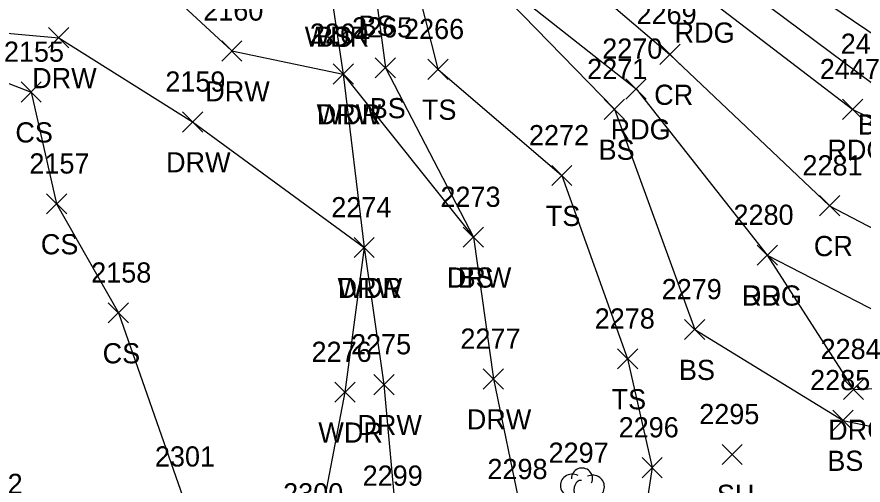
# Model space of a CAD drawing. Extents: x 1512665 to 1513714, y 110636 to 112816.
# Drawn here: x 1512914.5 to 1512998.3, y 110740.2 to 110786.6 of the extents above; entities that cross this region are included whole.
import ezdxf

# ---------------------------------------------------------------- set-up
doc = ezdxf.new("R2010")
doc.units = 0
for name, color, linetype in [('L_A', 7, 'Continuous'), ('L_I', 7, 'Continuous'), ('L_TIC', 7, 'Continuous'), ('LAWA', 7, 'Continuous'), ('LELB', 7, 'Continuous'), ('LTD', 7, 'Continuous'), ('P_A', 7, 'Continuous'), ('P_I', 7, 'Continuous'), ('P_TIC', 7, 'Continuous'), ('PEU', 7, 'Continuous'), ('PRC', 7, 'Continuous'), ('R_A', 7, 'Continuous'), ('R_I', 7, 'Continuous'), ('R_TIC', 7, 'Continuous'), ('RDG', 7, 'Continuous'), ('RDW', 7, 'Continuous')]:
    doc.layers.add(name, color=color, linetype=linetype)

msp = doc.modelspace()

# ---------------------------------------------------------------- linework, layer by layer
at = {"layer": 'L_TIC'}
for points in [[(1512949.992, 110780.568), (1512951.992, 110782.568)], [(1512951.992, 110780.568), (1512949.992, 110782.568)], [(1512949.992, 110780.568), (1512951.992, 110782.568)], [(1512951.992, 110780.568), (1512949.992, 110782.568)], [(1512955.195, 110780.418), (1512957.195, 110782.418)], [(1512957.195, 110780.418), (1512955.195, 110782.418)], [(1512945.819, 110779.951), (1512947.819, 110781.951)], [(1512947.819, 110779.951), (1512945.819, 110781.951)], [(1512914.917, 110778.166), (1512916.917, 110780.166)], [(1512916.917, 110778.166), (1512914.917, 110780.166)], [(1512972.652, 110776.453), (1512974.652, 110778.453)], [(1512974.652, 110776.453), (1512972.652, 110778.453)], [(1512967.46, 110769.893), (1512969.46, 110771.893)], [(1512969.46, 110769.893), (1512967.46, 110771.893)], [(1512917.439, 110767.088), (1512919.439, 110769.088)], [(1512919.439, 110767.088), (1512917.439, 110769.088)], [(1512958.698, 110763.789), (1512960.698, 110765.789)], [(1512960.698, 110763.789), (1512958.698, 110765.789)], [(1512947.89, 110762.758), (1512949.89, 110764.758)], [(1512949.89, 110762.758), (1512947.89, 110764.758)], [(1512923.557, 110756.288), (1512925.557, 110758.288)], [(1512925.557, 110756.288), (1512923.557, 110758.288)], [(1512980.607, 110754.641), (1512982.607, 110756.641)], [(1512982.607, 110754.641), (1512980.607, 110756.641)], [(1512973.971, 110751.732), (1512975.971, 110753.732)], [(1512975.971, 110751.732), (1512973.971, 110753.732)], [(1512945.989, 110748.434), (1512947.989, 110750.434)], [(1512947.989, 110748.434), (1512945.989, 110750.434)], [(1512995.294, 110745.637), (1512997.294, 110747.637)], [(1512997.294, 110745.637), (1512995.294, 110747.637)], [(1512984.316, 110742.266), (1512986.316, 110744.266)], [(1512986.316, 110742.266), (1512984.316, 110744.266)], [(1512976.394, 110740.958), (1512978.394, 110742.958)], [(1512978.394, 110740.958), (1512976.394, 110742.958)]]:
    msp.add_lwpolyline(points, dxfattribs=at)
at = {"layer": 'LAWA'}
msp.add_lwpolyline([(1512904.855, 110814.165), (1512921.132, 110807.474), (1512930.627, 110802.326), (1512939.473, 110793.102), (1512945.641, 110788.646), (1512946.819, 110780.951), (1512948.89, 110763.758), (1512946.989, 110749.434), (1512944.293, 110735.419), (1512940.962, 110714.938), (1512937.713, 110700.214), (1512950.792, 110688.786), (1512957.118, 110668.558), (1512971.82, 110659.404), (1512987.484, 110651.003), (1512993.751, 110649.548)], dxfattribs=at)
at = {"layer": 'LELB'}
for points in [[(1512700.679, 110948.394), (1512702.883, 110937.76), (1512707.699, 110928.255), (1512715.725, 110919.825), (1512729.364, 110912.396), (1512733.114, 110910.816), (1512749.564, 110901.484), (1512765.39, 110894.395), (1512774.129, 110890.874), (1512779.73, 110888.581), (1512784.329, 110885.95), (1512807.054, 110874.728), (1512832.029, 110862.151), (1512849.873, 110852.9), (1512877.541, 110837.789), (1512892.067, 110830.383), (1512907.918, 110822.224), (1512921.56, 110815.361), (1512936.611, 110807.627), (1512945.797, 110795.178), (1512949.896, 110789.739), (1512950.992, 110781.568)], [(1512965.768, 110809.049), (1512985.021, 110794.556), (1513002.316, 110782.838), (1513012.084, 110779.37), (1513025.948, 110772.452), (1513031.778, 110776.166)], [(1512936.611, 110807.627), (1512953.599, 110791.643), (1512956.195, 110781.418), (1512968.46, 110770.893), (1512974.971, 110752.732), (1512977.394, 110741.958), (1512974.26, 110721.428)], [(1512964.105, 110806.986), (1512983.29, 110791.889), (1512999.323, 110779.951), (1513012.212, 110774.48), (1513024.663, 110768.294), (1513032.242, 110771.906), (1513035.849, 110774.486)], [(1512958.132, 110793.433), (1512973.652, 110777.453), (1512981.607, 110755.641), (1512996.294, 110746.637), (1513006.992, 110744.376), (1513016.029, 110743.308), (1513026.953, 110745.673), (1513036.177, 110748.289)], [(1512902.912, 110747.196), (1512898.685, 110764.287), (1512894.988, 110776.221), (1512897.015, 110786.49), (1512915.917, 110779.166), (1512918.439, 110768.088), (1512924.557, 110757.288), (1512930.943, 110739.067), (1512912.467, 110736.35), (1512889.78, 110732.876)], [(1512950.992, 110781.568), (1512959.698, 110764.789)]]:
    msp.add_lwpolyline(points, dxfattribs=at)
at = {"layer": 'LTD'}
msp.add_arc((1512970.447, 110740.874), 1.047, 335.52715, 180.95627, dxfattribs=at)
for centre, major_axis, ratio, start_param, end_param in [((1512969.608, 110740.106), (1.21, -0.512), 0.895232, 1.570796, 4.712389), ((1512971.441, 110740.023), (-1.141, -0.483), 0.949671, 1.570796, 4.712389), ((1512970.191, 110739.898), (-0.208, -0.792), 0.645439, 3.141593, 6.283185)]:
    msp.add_ellipse(centre, major_axis=major_axis, ratio=ratio, start_param=start_param, end_param=end_param, dxfattribs=at)
at = {"layer": 'P_TIC'}
for points in [[(1512978.162, 110781.894), (1512980.162, 110783.894)], [(1512980.162, 110781.894), (1512978.162, 110783.894)], [(1512974.798, 110778.469), (1512976.798, 110780.469)], [(1512976.798, 110778.469), (1512974.798, 110780.469)], [(1512996.253, 110776.445), (1512998.253, 110778.445)], [(1512998.253, 110776.445), (1512996.253, 110778.445)], [(1512993.968, 110766.907), (1512995.968, 110768.907)], [(1512995.968, 110766.907), (1512993.968, 110768.907)], [(1512987.794, 110762.009), (1512989.794, 110764.009)], [(1512989.794, 110762.009), (1512987.794, 110764.009)]]:
    msp.add_lwpolyline(points, dxfattribs=at)
at = {"layer": 'PEU'}
for points in [[(1512701.918, 111049.687), (1512700.272, 111027.695), (1512701.575, 110993.777), (1512707.634, 110973.739), (1512708.973, 110956.468), (1512713.567, 110946.899), (1512719.219, 110936.541), (1512726.895, 110929.376), (1512741.614, 110919.596), (1512758.159, 110912.379), (1512787.354, 110896.005), (1512813.053, 110887.984), (1512838.367, 110874.777), (1512855.917, 110864.835), (1512882.817, 110848.349), (1512898.24, 110841.366), (1512913.486, 110833.402), (1512927.92, 110827.382), (1512944.462, 110817.212), (1512962.879, 110803.833), (1512982.126, 110789.052), (1512997.253, 110777.445), (1513011.324, 110770.561), (1513024.004, 110765.991)], [(1512908.545, 110823.763), (1512922.462, 110816.848), (1512937.29, 110809.107), (1512956.028, 110794.571), (1512958.132, 110793.433), (1512975.798, 110779.469), (1512988.794, 110763.009), (1513002.098, 110756.133), (1513012.974, 110751.731), (1513022.336, 110752.03), (1513042.715, 110756.056), (1513045.977, 110758.546), (1513043.773, 110764.486), (1513041.72, 110768.766), (1513036.521, 110767.718), (1513024.004, 110765.991)]]:
    msp.add_lwpolyline(points, dxfattribs=at)
at = {"layer": 'PRC'}
msp.add_lwpolyline([(1512910.919, 110828.697), (1512924.695, 110822.052), (1512939.408, 110813.161), (1512959.787, 110799.435), (1512979.162, 110782.894), (1512994.968, 110767.907), (1513005.499, 110762.392), (1513013.716, 110758.318), (1513024.25, 110758.228), (1513034.128, 110760.688), (1513043.773, 110764.486)], dxfattribs=at)
at = {"layer": 'R_TIC'}
for points in [[(1512917.649, 110783.546), (1512919.649, 110785.546)], [(1512919.649, 110783.546), (1512917.649, 110785.546)], [(1512934.784, 110782.238), (1512936.784, 110784.238)], [(1512936.784, 110782.238), (1512934.784, 110784.238)], [(1512945.819, 110779.951), (1512947.819, 110781.951)], [(1512947.819, 110779.951), (1512945.819, 110781.951)], [(1512930.904, 110775.206), (1512932.904, 110777.206)], [(1512932.904, 110775.206), (1512930.904, 110777.206)], [(1512958.698, 110763.789), (1512960.698, 110765.789)], [(1512960.698, 110763.789), (1512958.698, 110765.789)], [(1512947.89, 110762.758), (1512949.89, 110764.758)], [(1512949.89, 110762.758), (1512947.89, 110764.758)], [(1512987.794, 110762.009), (1512989.794, 110764.009)], [(1512989.794, 110762.009), (1512987.794, 110764.009)], [(1512949.846, 110749.182), (1512951.846, 110751.182)], [(1512951.846, 110749.182), (1512949.846, 110751.182)], [(1512960.676, 110749.74), (1512962.676, 110751.74)], [(1512962.676, 110749.74), (1512960.676, 110751.74)], [(1512996.328, 110748.713), (1512998.328, 110750.713)], [(1512998.328, 110748.713), (1512996.328, 110750.713)]]:
    msp.add_lwpolyline(points, dxfattribs=at)
at = {"layer": 'RDG'}
msp.add_lwpolyline([(1512988.794, 110763.009), (1512997.328, 110749.713), (1513005.245, 110750.054), (1513012.974, 110751.731)], dxfattribs=at)
at = {"layer": 'RDW'}
for points in [[(1512900.459, 110800.085), (1512923.203, 110794.904), (1512935.784, 110783.238), (1512946.819, 110780.951), (1512959.698, 110764.789), (1512961.676, 110750.74), (1512964.35, 110737.826), (1512956.004, 110719.217), (1512960.653, 110706.287), (1512964.16, 110695.737), (1512971.265, 110683.804), (1512977.643, 110679.977), (1512982.193, 110667.902), (1512995.78, 110663.608), (1513006.943, 110650.515)], [(1512897.015, 110786.49), (1512918.649, 110784.546), (1512931.904, 110776.206), (1512948.89, 110763.758), (1512950.846, 110750.182), (1512952.005, 110737.168), (1512942.845, 110714.997), (1512948.542, 110701.566), (1512954.882, 110691.814), (1512956.603, 110681.05), (1512965.489, 110667.959), (1512975.923, 110658.132), (1512992.247, 110654.447), (1512993.751, 110649.548)]]:
    msp.add_lwpolyline(points, dxfattribs=at)

# ---------------------------------------------------------------- texts
at = {"layer": 'L_A'}
for s, p in [('BS', (1512948.337, 110784.739)), ('WDR', (1512943.003, 110783.646)), ('BS', (1512944.082, 110783.646)), ('WDR', (1512944.182, 110775.951)), ('BS', (1512949.433, 110776.568)), ('BS', (1512949.433, 110776.568)), ('TS', (1512954.604, 110776.418)), ('BS', (1512997.764, 110774.951)), ('CS', (1512914.358, 110774.166)), ('BS', (1512972.093, 110772.453)), ('TS', (1512966.87, 110765.893)), ('CS', (1512916.88, 110763.088)), ('BS', (1512958.139, 110759.789)), ('WDR', (1512946.252, 110758.758)), ('CS', (1512922.998, 110752.288)), ('BS', (1512980.048, 110750.641)), ('TS', (1512973.381, 110747.732)), ('WDR', (1512944.352, 110744.434)), ('BS', (1512994.735, 110741.637)), ('SH', (1512983.805, 110738.266))]:
    msp.add_text(s, height=2, dxfattribs=at).set_placement(p)
at = {"layer": 'L_I'}
for s, p in [('2265', (1512947.685, 110784.568)), ('2265', (1512947.685, 110784.568)), ('2266', (1512952.833, 110784.418)), ('2264', (1512943.512, 110783.951)), ('2448', (1512996.064, 110782.951)), ('2155', (1512913.224, 110782.166)), ('2271', (1512970.96, 110780.453)), ('2272', (1512965.2, 110773.893)), ('2157', (1512915.746, 110771.088)), ('2273', (1512956.438, 110767.789)), ('2274', (1512945.63, 110766.758)), ('2158', (1512921.864, 110760.288)), ('2279', (1512978.339, 110758.641)), ('2278', (1512971.711, 110755.732)), ('2276', (1512943.674, 110752.434)), ('2285', (1512993.034, 110749.637)), ('2295', (1512982.057, 110746.266)), ('2296', (1512974.079, 110744.958)), ('2297', (1512967.14, 110742.44)), ('2301', (1512928.171, 110742.067)), ('2301', (1512928.171, 110742.067)), ('2302', (1512909.128, 110739.35)), ('2300', (1512940.868, 110738.419))]:
    msp.add_text(s, height=2, dxfattribs=at).set_placement(p)
at = {"layer": 'P_A'}
for s, p in [('RDG', (1512979.614, 110784.052)), ('CR', (1512977.595, 110777.894)), ('RDG', (1512973.286, 110774.469)), ('RDG', (1512994.742, 110772.445)), ('CR', (1512993.402, 110762.907)), ('RDG', (1512986.282, 110758.009))]:
    msp.add_text(s, height=2, dxfattribs=at).set_placement(p)
at = {"layer": 'P_I'}
for s, p in [('2269', (1512975.847, 110785.894)), ('2270', (1512972.451, 110782.469)), ('2447', (1512993.994, 110780.445)), ('2281', (1512992.276, 110770.907)), ('2280', (1512985.447, 110766.009))]:
    msp.add_text(s, height=2, dxfattribs=at).set_placement(p)
at = {"layer": 'R_A'}
for s, p in [('DRW', (1512916.019, 110779.546)), ('DRW', (1512933.154, 110778.238)), ('DRW', (1512944.19, 110775.951)), ('DRW', (1512929.275, 110771.206)), ('DRW', (1512957.068, 110759.789)), ('DRW', (1512946.26, 110758.758)), ('DRG', (1512986.282, 110758.009)), ('DRW', (1512959.046, 110745.74)), ('DRW', (1512948.216, 110745.182)), ('DRG', (1512994.816, 110744.713))]:
    msp.add_text(s, height=2, dxfattribs=at).set_placement(p)
at = {"layer": 'R_I'}
for s, p in [('2160', (1512932.957, 110786.238)), ('2264', (1512943.512, 110783.951)), ('2159', (1512929.204, 110779.206)), ('2273', (1512956.438, 110767.789)), ('2274', (1512945.63, 110766.758)), ('2280', (1512985.447, 110766.009)), ('2277', (1512958.416, 110753.74)), ('2275', (1512947.586, 110753.182)), ('2284', (1512994.068, 110752.713)), ('2298', (1512961.09, 110740.826)), ('2299', (1512948.737, 110740.168))]:
    msp.add_text(s, height=2, dxfattribs=at).set_placement(p)

doc.saveas('drawing.dxf')
